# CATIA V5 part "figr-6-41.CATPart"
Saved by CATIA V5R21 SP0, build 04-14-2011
Part number: Part1
Bounding box of the stored display mesh (mm): x 0 to 45, y 0 to 76.536, z 0 to 111.001
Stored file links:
  D:\CATIA V5R21 E-RESOURCES\CATIA-V5R21\catia-v5r21-prt\c06-catia-v5r21-prt\c06-catia-v5r21-figr-6-41.CATPart
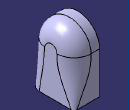
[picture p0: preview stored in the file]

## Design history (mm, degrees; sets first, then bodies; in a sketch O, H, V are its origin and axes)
Body1 (main body)
  Sketch1 on yz-plane, origin (0, 0, 0), H (0, 1, 0), V (0, 0, 1)
    line L1 (0, 0) -> (76.5361, 0)
    line L2 (76.5361, 0) -> (76.5361, 72.7325)
    line L3 (0, 0) -> (0, 72.7325)
    arc A1 centre (38.2681, 72.7325) radius 38.2681 from (76.5361, 72.7325) to (0, 72.7325) ccw
    horizontal: L1 H
    vertical: L2 V, L3 V
    tangency: A1 L3, A1 L2
  Pad1: profile Sketch1, direction (1, 0, 0), length 45
  Fillet1: on edge [face of Pad1 | face of Pad1] (x3)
